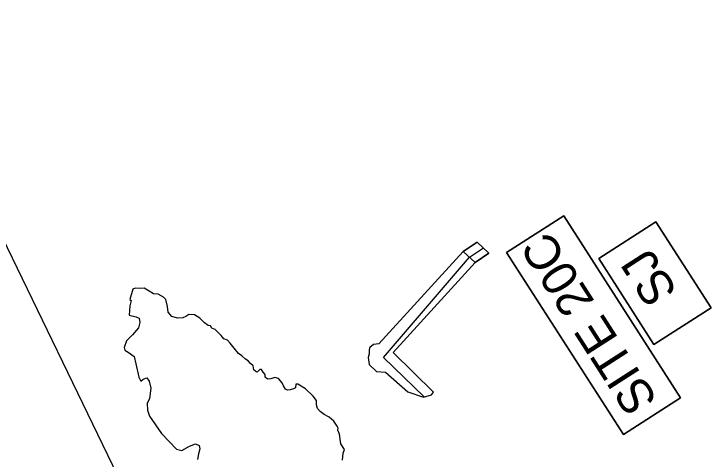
# Model space of a CAD drawing. Extents: x 474218 to 481634, y 484357 to 504997.
# Drawn here: x 477802 to 478100.6, y 499438.4 to 499629 of the extents above; entities that cross this region are included whole.
import ezdxf

# ---------------------------------------------------------------- set-up
doc = ezdxf.new("R2010")
doc.units = 0
for name, color, linetype in [('Exist Hydro Jurisdictional Stream or Body of Water', 7, 'Continuous'), ('Old_Level_29', 7, 'Continuous'), ('Prop Earthen Structure Impacts In Surface Waters Hatching CELL', 7, 'Continuous'), ('Prop Earthen Structure Impacts In Surface Waters Pond Hatching CELL', 7, 'Continuous'), ('Prop Grid Mask', 7, 'Continuous'), ('Scratch_Level_4', 7, 'Continuous'), ('Temp Earthen Structure Impacts In Surface Waters Hatching CELL', 7, 'Continuous')]:
    doc.layers.add(name, color=color, linetype=linetype)

msp = doc.modelspace()

# ---------------------------------------------------------------- linework, layer by layer
at = {"layer": 'Exist Hydro Jurisdictional Stream or Body of Water'}
msp.add_line((477857, 499409.77), (477750.58, 499628.95), dxfattribs=at)
msp.add_lwpolyline([(478076.13, 499487.41), (478052.52, 499524.21), (478077, 499539.92), (478100.61, 499503.11)], close=True, dxfattribs=at)
at = {"layer": 'Old_Level_29'}
msp.add_lwpolyline([(478063.05, 499448.86), (478013.02, 499526.85), (478037.51, 499542.56), (478087.54, 499464.57)], close=True, dxfattribs=at)
at = {"layer": 'Prop Earthen Structure Impacts In Surface Waters Hatching CELL'}
for p, q in [((477994.45, 499527.29), (477958.24, 499487.65)), ((477999.62, 499522.57), (477994.45, 499527.29)), ((477964.45, 499483.95), (477999.62, 499522.57)), ((477981.74, 499467), (477964.45, 499483.95))]:
    msp.add_line(p, q, dxfattribs=at)
msp.add_lwpolyline([(477958.24, 499487.65), (477956.05, 499487.44), (477954.41, 499486.18), (477954.21, 499485.09), (477954.16, 499483.5), (477953.69, 499481.87), (477954.09, 499478.91), (477957.37, 499475.93), (477961.18, 499475.57), (477970.72, 499467.23), (477977.41, 499464.91), (477980.85, 499465.85), (477981.74, 499467)], dxfattribs=at)
at = {"layer": 'Prop Earthen Structure Impacts In Surface Waters Pond Hatching CELL'}
msp.add_lwpolyline([(477942.71, 499437.86), (477943, 499440.93), (477943.59, 499442.46), (477942.08, 499444.89), (477941.45, 499449.06), (477940.78, 499450.71), (477940.84, 499451.68), (477940.4, 499452.51), (477938.99, 499454.62), (477937.06, 499456.39), (477934.92, 499457.48), (477933.13, 499458.74), (477932.01, 499460.06), (477931.57, 499461.63), (477931.54, 499463.39), (477930.12, 499465.3), (477926.91, 499468.47), (477923.55, 499470.51), (477922.76, 499470.43), (477922.58, 499468.88), (477921.8, 499468.52), (477920.32, 499467.97), (477919.12, 499467.9), (477918.25, 499468.34), (477917.51, 499469.76), (477916.86, 499471.07), (477915.33, 499472.88), (477913.71, 499473.31), (477911.97, 499472.75), (477910.58, 499472.62), (477909.6, 499473.43), (477909.61, 499474.59), (477908.8, 499475.52), (477908.05, 499476.74), (477907.31, 499476.73), (477906.2, 499475.6), (477905.77, 499475.68), (477904.75, 499476.62), (477904.4, 499478.35), (477903.3, 499479.34), (477902.3, 499480.48), (477901.15, 499481.18), (477899.68, 499482.53), (477898.17, 499483.53), (477896.37, 499485.81), (477894.59, 499488.02), (477893.41, 499489.32), (477891.96, 499489.86), (477890.73, 499491.35), (477888.17, 499493.89), (477886.74, 499494.37), (477886.24, 499495.45), (477885.23, 499495.64), (477883.62, 499496.75), (477881.62, 499498.77), (477879.39, 499500.17), (477876.87, 499500.21), (477875.65, 499499.46), (477874.38, 499498.89), (477872.07, 499498.65), (477869.56, 499499.36), (477868.07, 499501.26), (477867.83, 499503.77), (477867.08, 499506.69), (477866.05, 499507.69), (477863.83, 499509.03), (477861.75, 499509.19), (477859.95, 499510.24), (477857.8, 499511.61), (477856.01, 499511.44), (477853.86, 499511.58), (477852.97, 499511.13), (477851.69, 499506.75), (477852.19, 499506.21), (477851.59, 499504), (477851.36, 499500), (477854.33, 499499.34), (477855.61, 499498.68), (477855.92, 499496.87), (477855.36, 499494.53), (477852.73, 499491.54), (477850.25, 499489.01), (477849.21, 499486.2), (477849.55, 499485), (477850.96, 499484.11), (477853.53, 499482.25), (477854.27, 499479.13), (477855.53, 499473.5), (477856.38, 499471.7), (477857.29, 499472.57), (477858.89, 499473.16), (477859.85, 499471.67), (477860.63, 499468.69), (477860.01, 499464.37), (477859, 499462.18), (477859.14, 499459.29), (477860.12, 499456.78), (477865.22, 499449.32), (477871.69, 499442.58), (477873.96, 499442), (477877.22, 499443.94), (477879.74, 499444.86), (477881.29, 499444.21), (477881.62, 499442.81), (477881.08, 499440.62), (477880.68, 499438.19)], dxfattribs=at)
at = {"layer": 'Prop Grid Mask'}
for points in [[(478087.54, 499464.57), (478037.51, 499542.56), (478013.02, 499526.85), (478063.05, 499448.86)], [(478100.61, 499503.11), (478077, 499539.92), (478052.52, 499524.21), (478076.13, 499487.41)]]:
    msp.add_lwpolyline(points, close=True, dxfattribs=at)
at = {"layer": 'Scratch_Level_4'}
for p, q in [((477999.62, 499522.57), (477994.45, 499527.29)), ((477981.74, 499467), (477964.45, 499483.95))]:
    msp.add_line(p, q, dxfattribs=at)
msp.add_lwpolyline([(478005.48, 499526.49), (477999.62, 499522.57), (477994.45, 499527.29), (478000.41, 499531.31)], close=True, dxfattribs=at)
for points in [[(477994.45, 499527.29), (477958.24, 499487.65)], [(477997.08, 499524.88), (477997.08, 499524.88), (478003.13, 499528.76)], [(477977.65, 499464.98), (477960.25, 499481.8), (477997.08, 499524.88)], [(477964.45, 499483.95), (477999.62, 499522.57)], [(477958.24, 499487.65), (477956.05, 499487.44), (477954.41, 499486.18), (477954.21, 499485.09), (477954.16, 499483.5), (477953.69, 499481.87), (477954.09, 499478.91), (477957.37, 499475.93), (477961.18, 499475.57), (477970.72, 499467.23), (477977.41, 499464.91), (477980.85, 499465.85), (477981.74, 499467)]]:
    msp.add_lwpolyline(points, dxfattribs=at)
at = {"layer": 'Temp Earthen Structure Impacts In Surface Waters Hatching CELL'}
for p, q in [((477994.45, 499527.29), (477999.62, 499522.57)), ((477999.62, 499522.57), (478005.48, 499526.49))]:
    msp.add_line(p, q, dxfattribs=at)
msp.add_lwpolyline([(478005.48, 499526.49), (478000.41, 499531.31), (477994.45, 499527.29)], dxfattribs=at)

# ---------------------------------------------------------------- texts
at = {"layer": 'Exist Hydro Jurisdictional Stream or Body of Water'}
msp.add_text('SJ', height=15, rotation=122.6822, dxfattribs=at).set_placement((478086.61, 499510.14))
at = {"layer": 'Old_Level_29'}
msp.add_text('SITE 20C', height=15, rotation=122.6822, dxfattribs=at).set_placement((478078.08, 499463.59))

doc.saveas('drawing.dxf')
